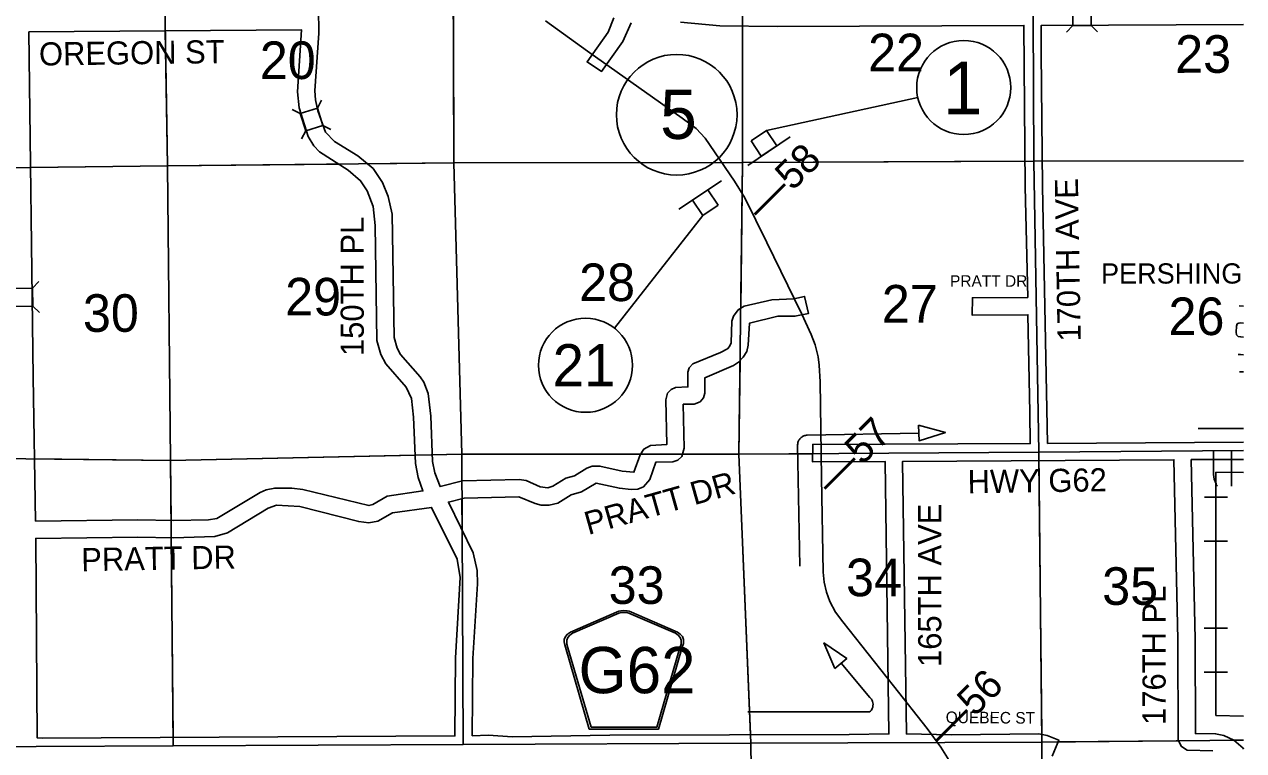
# Model space of a CAD drawing. Extents: x 10133 to 81668, y 5524 to 11018.
# Drawn here: x 22283 to 22810, y 9046 to 9359 of the extents above; entities that cross this region are included whole.
import ezdxf

# ---------------------------------------------------------------- set-up
doc = ezdxf.new("R2010")
doc.units = 0
for name, color, linetype in [('Default', 7, 'Continuous'), ('DisBoundDim', 7, 'Continuous'), ('DisCLMLOR', 7, 'Continuous'), ('DisCLMLSUR', 7, 'Continuous'), ('trf_SignNumber_Text', 7, 'Continuous')]:
    doc.layers.add(name, color=color, linetype=linetype)

msp = doc.modelspace()

# ---------------------------------------------------------------- linework, layer by layer
at = {"layer": 'Default'}
for p, q in [((22736.61, 9358.91), (22733.85, 9356.13)), ((22744.43, 9358.92), (22747.21, 9356.16)), ((22410.04, 9323.23), (22411.83, 9326.71)), ((22402.58, 9320.86), (22399.11, 9322.66)), ((22404.95, 9313.4), (22403.16, 9309.93)), ((22412.41, 9315.77), (22415.88, 9313.98)), ((22286.91, 9245.48), (22289.62, 9248.3)), ((22287.05, 9237.66), (22289.87, 9234.94)), ((22803.47, 9155.18), (22793.41, 9155.18)), ((22803.47, 9136.15), (22793.39, 9136.15)), ((22803.46, 9098.49), (22793.4, 9098.49)), ((22803.46, 9079.46), (22793.37, 9079.46))]:
    msp.add_line(p, q, dxfattribs=at)
for points in [[(22343.21, 9423.31), (22345.2, 9298.26)], [(22468.62, 9423.7), (22469.06, 9299.65)], [(22593.7, 9425.52), (22593.82, 9299.69)], [(22719.06, 9425.1), (22719.65, 9300.38)], [(22409.76, 9419.76), (22410.63, 9355.71), (22408.86, 9330.7), (22409.14, 9326.81), (22410.24, 9322.02), (22413.56, 9312.82), (22417.41, 9308.79), (22427.56, 9302.62), (22434.1, 9297.1), (22438.17, 9291.06), (22440.65, 9285.08), (22442.28, 9277.38), (22443.16, 9224.11), (22444.43, 9219.59), (22445.89, 9216.81), (22454.49, 9207.13), (22455.98, 9204.85), (22457.9, 9199.92), (22459.06, 9190.16), (22459.8, 9170.58), (22460.79, 9165.69), (22463.07, 9159.69), (22472.74, 9162.19), (22497.29, 9162.82), (22500.2, 9162.38), (22506.24, 9159.59), (22509.58, 9159.15), (22511.82, 9159.89), (22517.41, 9163.31), (22521.15, 9164.37), (22526.5, 9167.61), (22528.81, 9168.46), (22532.14, 9168.57), (22541.79, 9166.35), (22546.86, 9165.93), (22549.48, 9173.49), (22551.11, 9175.88), (22553.99, 9177.44), (22561, 9177.86), (22560.67, 9197.25), (22561.4, 9200.08), (22562.92, 9201.67), (22564.77, 9202.48), (22570.14, 9202.77), (22570.07, 9209.21), (22570.7, 9211.09), (22572.25, 9212.8), (22584.29, 9217.6), (22587.25, 9219.23), (22588.19, 9220.27), (22588.86, 9221.85), (22589.17, 9231.12), (22589.85, 9233.3), (22591.94, 9236.14), (22594.51, 9237.74), (22606.5, 9240.45), (22615.89, 9240.79), (22620.59, 9241.87), (22622.31, 9234.57), (22616.41, 9233.29), (22609.09, 9233.31), (22596.8, 9230.33), (22596.29, 9220.77), (22595.58, 9218.11), (22594.09, 9215.63), (22592.09, 9213.47), (22589.82, 9212.01), (22577.53, 9206.76), (22577.52, 9200.11), (22576.92, 9198.1), (22575.4, 9196.36), (22572.84, 9195.36), (22568.18, 9195.25), (22568.51, 9176.31), (22567.57, 9172.64), (22565.75, 9171.06), (22563.7, 9170.37), (22556.28, 9170.21), (22553.7, 9162.75), (22550.95, 9159.53), (22548.58, 9158.53), (22545.59, 9158.42), (22540.58, 9158.95), (22530.54, 9161.14), (22524.23, 9157.5), (22519.71, 9156.1), (22513.9, 9152.54), (22510.19, 9151.67), (22506.73, 9151.74), (22504.2, 9152.38), (22497.15, 9155.32), (22473.5, 9154.73), (22466.67, 9152.97), (22477.4, 9131.1), (22479.02, 9123.47), (22479.2, 9117.62), (22477.16, 9085.44), (22476.94, 9052.05), (22483.99, 9052.21), (22494.18, 9051.59), (22536.42, 9052.23)], [(22468.65, 9413.36), (22469.06, 9299.65)], [(22508.58, 9360.95), (22526.77, 9347.85), (22567.7, 9318.96), (22573.78, 9314.39), (22577.63, 9310.27), (22590.3, 9291.68), (22594.77, 9284.47), (22604.23, 9265.23), (22619.37, 9234.22), (22623.5, 9225.36), (22625.14, 9221), (22626.5, 9215.72), (22626.98, 9212.22), (22627.29, 9205.03), (22627.94, 9163.63), (22628.65, 9122.7), (22629.08, 9118.35), (22630.07, 9114.09), (22631.58, 9110), (22634.01, 9105.46), (22637.15, 9101.24), (22659.01, 9073.59), (22673.56, 9055.16), (22679.54, 9047.08), (22683.05, 9041.35)], [(22545.62, 9360.09), (22542.07, 9352.03), (22532.87, 9339.09), (22526.62, 9343.23), (22535.74, 9356.05), (22538.2, 9362.29)], [(22536.42, 9052.23), (22639.94, 9052.58), (22657.09, 9052.79), (22655.49, 9170.52), (22623.97, 9170.46), (22624.11, 9177.96), (22718.16, 9178.31), (22718.03, 9191.78), (22717.17, 9233.95), (22693.03, 9233.84), (22693.13, 9241.34), (22717.04, 9241.44), (22715.94, 9289.26), (22715.44, 9358.96), (22608.91, 9358.52), (22583.94, 9358.86), (22566.92, 9360.42)], [(22332.33, 9145.28), (22347.76, 9145.04), (22363, 9145.36), (22366.5, 9145.92), (22385.22, 9157.09), (22387.9, 9158.29), (22391.58, 9159.08), (22399.01, 9159.06), (22403.78, 9158.43), (22432.27, 9151.51), (22434.05, 9152), (22440.13, 9155.51), (22455.66, 9157.81), (22453.58, 9163.62), (22452.36, 9169.68), (22451.59, 9189.63), (22450.7, 9197.8), (22448.43, 9202.7), (22439.55, 9212.8), (22437.46, 9216.83), (22435.76, 9222.9), (22434.92, 9272.53), (22434.13, 9280.79), (22431.55, 9287.53), (22428.7, 9291.9), (22423.25, 9296.48), (22410.98, 9304.31), (22408.5, 9306.98), (22406.05, 9310.97), (22402.16, 9323.4), (22401.37, 9330.31), (22403.13, 9357.14), (22285.33, 9356.18), (22287.15, 9206.92), (22288.23, 9144.77), (22332.33, 9145.28)], [(22344.26, 9356.84), (22345.2, 9298.26)], [(22593.76, 9358.63), (22593.82, 9299.69)], [(22810.38, 9359.34), (22722.94, 9359), (22722.89, 9347.36), (22723.44, 9289.35), (22725.65, 9178.39), (22810.38, 9178.86)], [(21572.35, 9043.42), (21608.78, 9043.66), (21731.94, 9044.53), (21857.47, 9045.16), (21981.12, 9045.77), (22105.74, 9046.56), (22229.13, 9047.1), (22347.67, 9047.62), (22473.01, 9048.27), (22597.43, 9048.78), (22723.17, 9049.27), (22721.89, 9174.62), (22719.65, 9300.38), (22810.38, 9300.49)], [(22226.65, 9296.85), (22345.2, 9298.26)], [(22286.13, 9297.56), (22345.2, 9298.26)], [(22345.2, 9298.26), (22469.06, 9299.65)], [(22345.2, 9298.26), (22418.96, 9299.09)], [(22345.2, 9298.26), (22346.49, 9171.02)], [(22345.2, 9298.26), (22346.49, 9171.02)], [(22431.95, 9299.24), (22469.06, 9299.65)], [(22469.06, 9299.65), (22593.82, 9299.69)], [(22469.06, 9299.65), (22593.82, 9299.69)], [(22469.06, 9299.65), (22472.42, 9173.67)], [(22469.06, 9299.65), (22472.42, 9173.67)], [(22593.82, 9299.69), (22592.19, 9173.69)], [(22593.82, 9299.69), (22593, 9236.9)], [(22593.82, 9299.69), (22719.65, 9300.38)], [(22593.82, 9299.69), (22715.94, 9300.36)], [(22719.65, 9300.38), (22810.38, 9300.49)], [(22719.65, 9300.38), (22721.89, 9174.62)], [(22723.4, 9300.38), (22810.38, 9300.49)], [(22723.44, 9300.38), (22810.38, 9300.49)], [(22808.45, 9237.76), (22810.28, 9237.67), (22810.38, 9237.67)], [(22810.38, 9230.39), (22809.16, 9230.48), (22808.27, 9230.39), (22807.89, 9230.17), (22807.64, 9230.03), (22807.29, 9229.05), (22807.15, 9226.37), (22807.37, 9225.25), (22808, 9224.63), (22809.16, 9224.36), (22810.38, 9224.22)], [(22592.71, 9214.13), (22592.19, 9173.69)], [(22808, 9216.85), (22809.03, 9216.81), (22810.38, 9216.63)], [(22808.54, 9209.35), (22810.38, 9209.29)], [(22618.53, 9125.27), (22617.6, 9177.69), (22617.62, 9178.14), (22617.66, 9178.42), (22617.73, 9178.77), (22617.84, 9179.12), (22617.98, 9179.46), (22618.14, 9179.78), (22618.34, 9180.09), (22618.56, 9180.38), (22618.81, 9180.65), (22619.08, 9180.9), (22619.37, 9181.12), (22619.67, 9181.32), (22620, 9181.48), (22620.34, 9181.62), (22620.69, 9181.73), (22621.04, 9181.81), (22621.4, 9181.85), (22621.77, 9181.86), (22669.99, 9182.8)], [(22790.79, 9184.86), (22810.38, 9184.83)], [(22233.66, 9172.34), (22346.49, 9171.02)], [(22287.78, 9171.7), (22346.49, 9171.02)], [(22346.49, 9171.02), (22472.42, 9173.67)], [(22346.49, 9171.02), (22452.12, 9173.24)], [(22346.49, 9171.02), (22346.74, 9145.06)], [(22346.49, 9171.02), (22347.67, 9047.62)], [(22459.62, 9173.4), (22472.42, 9173.67)], [(22472.42, 9173.67), (22592.19, 9173.69)], [(22472.42, 9173.67), (22549.59, 9173.68)], [(22472.42, 9173.67), (22472.48, 9162.15)], [(22472.42, 9173.67), (22473.01, 9048.27)], [(22568.02, 9173.69), (22592.19, 9173.69)], [(22592.19, 9173.69), (22721.89, 9174.62)], [(22592.19, 9173.69), (22624.04, 9173.92)], [(22592.19, 9173.69), (22597.27, 9052.53)], [(22592.19, 9173.69), (22597.43, 9048.78)], [(22797.07, 9045.51), (22785.91, 9045.76), (22783.47, 9047.31), (22782.15, 9050.11), (22782.01, 9093.63), (22780.22, 9171.29), (22662.99, 9170.59), (22664.59, 9052.81), (22684.17, 9052.45), (22721.81, 9052.9), (22725.42, 9052.2), (22730.47, 9050.12), (22727.62, 9043.19)], [(22721.89, 9174.62), (22810.38, 9175.3)], [(22721.89, 9174.62), (22723.17, 9049.27)], [(22723.14, 9052.68), (22721.92, 9170.87)], [(22721.92, 9170.83), (22723.14, 9052.64)], [(22810.38, 9171.47), (22787.72, 9171.36), (22789.5, 9093.76), (22789.58, 9052.94), (22798.27, 9052.92), (22801.76, 9052.15), (22806.14, 9050.14), (22810.12, 9046.62), (22810.38, 9046.18)], [(22799.07, 9160.09), (22798.79, 9160.24), (22798.58, 9160.49), (22798.45, 9160.86), (22797.68, 9162.96), (22797.53, 9163.85), (22797.41, 9164.87), (22797.41, 9166.01), (22797.41, 9169.27), (22797.38, 9175.2)], [(22805.17, 9159.87), (22805.09, 9175.15)], [(22810.38, 9060.46), (22798.41, 9060.83), (22798.44, 9165.89), (22810.38, 9165.81)], [(22798.43, 9155.18), (22798.44, 9165.89), (22810.38, 9165.81)], [(22472.51, 9154.61), (22472.58, 9140.12)], [(22290.98, 9051.03), (22469.44, 9051.94), (22469.67, 9085.7), (22471.74, 9120.46), (22470.43, 9128.32), (22459.4, 9150.69), (22442.46, 9148.36), (22436.21, 9144.73), (22432.24, 9144), (22427.92, 9144.58), (22402.44, 9151.05), (22392.35, 9151.61), (22388.68, 9150.44), (22371.22, 9139.77), (22365.63, 9138.09), (22347.83, 9137.54), (22332.35, 9137.78), (22288.25, 9137.27), (22288.89, 9051.06), (22290.98, 9051.03)], [(22346.81, 9137.56), (22347.63, 9051.36)], [(22798.42, 9098.49), (22798.43, 9136.15)], [(22596.07, 9062.43), (22648.72, 9062.35), (22649.04, 9062.67), (22649.47, 9063.13), (22649.83, 9063.83), (22650.06, 9064.45), (22650.14, 9065.02), (22650.19, 9065.65), (22650.15, 9066.26), (22649.98, 9066.8), (22649.8, 9067.29), (22649.56, 9067.77), (22648.88, 9068.53), (22636.44, 9083.36)], [(22810.38, 9060.46), (22798.41, 9060.83), (22798.42, 9079.46)], [(22597.43, 9048.78), (22723.17, 9049.27)], [(22723.17, 9049.27), (22810.38, 9050.19)], [(22723.17, 9049.27), (22724.27, 8920.71)], [(22730.16, 9049.35), (22782.22, 9049.89)], [(22806.14, 9050.14), (22810.38, 9050.19)], [(22229.13, 9047.1), (22347.67, 9047.62)], [(22347.67, 9047.62), (22473.01, 9048.27)], [(22473.01, 9048.27), (22597.43, 9048.78)], [(22599.14, 8920.44), (22597.43, 9048.78)]]:
    msp.add_lwpolyline(points, dxfattribs=at)
for points in [[(22736.59, 9366.73), (22744.42, 9366.74), (22744.43, 9358.92), (22736.61, 9358.91)], [(22404.95, 9313.4), (22402.58, 9320.86), (22410.04, 9323.23), (22412.41, 9315.77)], [(22279.23, 9237.51), (22279.08, 9245.33), (22286.91, 9245.48), (22287.05, 9237.66)], [(22669.89, 9186.27), (22681.51, 9183.06), (22670.07, 9179.53)], [(22527.56, 9054.88), (22517.32, 9090.24), (22516.83, 9091.88), (22516.74, 9092.62), (22516.74, 9093.6), (22517.27, 9094.88), (22518.18, 9095.95), (22519.38, 9096.78), (22540.29, 9105.82), (22541.23, 9106.03), (22542.53, 9106.14), (22543.83, 9106.03), (22544.77, 9105.82), (22565.68, 9096.78), (22566.88, 9095.95), (22567.79, 9094.88), (22568.32, 9093.6), (22568.32, 9092.62), (22568.23, 9091.88), (22567.74, 9090.24), (22557.5, 9054.88)], [(22528.29, 9055.67), (22518.33, 9090.08), (22517.86, 9091.66), (22517.77, 9092.36), (22517.77, 9093.3), (22518.28, 9094.54), (22519.15, 9095.56), (22520.3, 9096.36), (22540.38, 9105.04), (22541.28, 9105.24), (22542.53, 9105.34), (22543.78, 9105.24), (22544.68, 9105.04), (22564.76, 9096.36), (22565.9, 9095.56), (22566.78, 9094.54), (22567.29, 9093.3), (22567.29, 9092.36), (22567.2, 9091.66), (22566.73, 9090.08), (22556.77, 9055.67)], [(22633.74, 9081.11), (22628.93, 9092.16), (22638.86, 9085.48)]]:
    msp.add_lwpolyline(points, close=True, dxfattribs=at)
msp.add_circle((22565.34, 9320.41), 26.06, dxfattribs=at)
at = {"layer": 'DisBoundDim'}
for p, q in [((22604.11, 9313.54), (22597.46, 9309.1)), ((22608.55, 9306.89), (22604.11, 9313.54)), ((22614.43, 9310.81), (22596.02, 9298.52)), ((22601.9, 9302.45), (22597.46, 9309.1)), ((22566.28, 9279.57), (22584.69, 9291.86)), ((22578.81, 9287.94), (22583.25, 9281.28)), ((22572.16, 9283.49), (22576.6, 9276.84)), ((22576.6, 9276.84), (22583.25, 9281.28))]:
    msp.add_line(p, q, dxfattribs=at)
at = {"layer": 'DisCLMLOR'}
for p, q in [((22604.11, 9313.54), (22597.46, 9309.1)), ((22604.11, 9313.54), (22597.46, 9309.1)), ((22604.11, 9313.54), (22597.46, 9309.1)), ((22604.11, 9313.54), (22597.46, 9309.1)), ((22608.55, 9306.89), (22604.11, 9313.54)), ((22608.55, 9306.89), (22604.11, 9313.54)), ((22608.55, 9306.89), (22604.11, 9313.54)), ((22608.55, 9306.89), (22604.11, 9313.54)), ((22597.46, 9309.1), (22601.9, 9302.45)), ((22597.46, 9309.1), (22601.9, 9302.45)), ((22597.46, 9309.1), (22601.9, 9302.45)), ((22597.46, 9309.1), (22601.9, 9302.45)), ((22601.9, 9302.45), (22608.55, 9306.89)), ((22601.9, 9302.45), (22608.55, 9306.89)), ((22601.9, 9302.45), (22608.55, 9306.89)), ((22601.9, 9302.45), (22608.55, 9306.89)), ((22578.81, 9287.94), (22572.16, 9283.49)), ((22578.81, 9287.94), (22572.16, 9283.49)), ((22578.81, 9287.94), (22572.16, 9283.49)), ((22578.81, 9287.94), (22572.16, 9283.49)), ((22583.25, 9281.28), (22578.81, 9287.94)), ((22583.25, 9281.28), (22578.81, 9287.94)), ((22583.25, 9281.28), (22578.81, 9287.94)), ((22583.25, 9281.28), (22578.81, 9287.94)), ((22572.16, 9283.49), (22576.6, 9276.84)), ((22572.16, 9283.49), (22576.6, 9276.84)), ((22572.16, 9283.49), (22576.6, 9276.84)), ((22572.16, 9283.49), (22576.6, 9276.84)), ((22576.6, 9276.84), (22583.25, 9281.28)), ((22576.6, 9276.84), (22583.25, 9281.28)), ((22576.6, 9276.84), (22583.25, 9281.28)), ((22576.6, 9276.84), (22583.25, 9281.28))]:
    msp.add_line(p, q, dxfattribs=at)
at = {"layer": 'DisCLMLSUR'}
for p, q in [((22604.11, 9313.54), (22669.53, 9327.82)), ((22576.6, 9276.84), (22538.45, 9228.13))]:
    msp.add_line(p, q, dxfattribs=at)
at = {"layer": 'trf_SignNumber_Text'}
for centre in [(22689.39, 9332.15), (22525.92, 9212.12)]:
    msp.add_circle(centre, 20.33, dxfattribs=at)

# ---------------------------------------------------------------- texts
at = {"layer": 'Default'}
for s, height, rotation, p in [('22', 16.25, 0.019, (22648.06, 9339.17)), ('23', 16.25, 0.0198, (22780.81, 9338.5)), ('OREGON ST', 10, 0.7616, (22289.73, 9341.63)), ('20', 16.25, 0.0174, (22385.12, 9335.82)), ('‒‒58', 12.5, 45, (22602.27, 9273.99)), ('170TH AVE', 10, 91, (22739.99, 9222.45)), ('150TH PL', 10, 90, (22430.07, 9216.11)), ('28', 16.25, 0.0182, (22523.16, 9239.85)), ('PERSHING', 8.75, 0.0197, (22748.74, 9247.41)), ('29', 16.25, 0.0176, (22396.08, 9233.64)), ('PRATT DR', 5, 0.0189, (22683.47, 9246.03)), ('27', 16.25, 0.019, (22653.99, 9230.57)), ('30', 16.25, 0.017, (22308.66, 9226.57)), ('26', 16.25, 0.0198, (22777.92, 9225.16)), ('‒‒57', 12.5, 45, (22632.44, 9155.53)), ('PRATT DR', 10, 15.704, (22527.11, 9138.74)), ('HWY G62', 10, 0.8527, (22691.14, 9156.79)), ('165TH AVE', 10, 90, (22679.7, 9081.73)), ('PRATT DR', 10, 1.0428, (22308.02, 9123.1)), ('34', 16.25, 0.0191, (22638.54, 9112.32)), ('33', 16.25, 0.0183, (22535.91, 9108.99)), ('35', 16.25, 0.0197, (22749.25, 9108.58)), ('176TH PL', 10, 90, (22776.67, 9056.7)), ('‒‒56', 12.5, 45, (22681, 9046.75)), ('QUEBEC ST', 5, 359.5734, (22681.59, 9057.51))]:
    msp.add_text(s, height=height, rotation=rotation, dxfattribs=at).set_placement(p)
for s, height, p in [('5', 21.25, (22558.17, 9309.93)), ('G62', 20, (22522.92, 9070.41))]:
    msp.add_text(s, height=height, dxfattribs=at).set_placement(p)
at = {"layer": 'trf_SignNumber_Text'}
for s, height, p in [('1', 22.82, (22680.49, 9320.54)), ('21', 18.258, (22511.69, 9202.99))]:
    msp.add_text(s, height=height, dxfattribs=at).set_placement(p)

doc.saveas('drawing.dxf')
